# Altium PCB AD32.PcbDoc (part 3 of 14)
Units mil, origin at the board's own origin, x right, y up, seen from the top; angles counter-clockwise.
Board outline 7007.87 x 4368.85 mil, 12 copper layers (Top Layer, Int1 (GND), Int2 (AVDD), Int3 (DVDD), Int4 (GND), Int5 (ST), Int6 (SB), Int8 (AGND), Int7 (AVCC), Int9 (VCCA), Int10 (GND), Bottom Layer), stack 60.136 mil thick; 1350 components, 880 nets, 4712 pads, 2835 vias.
Unrouted connection lines stored in the file: 19.
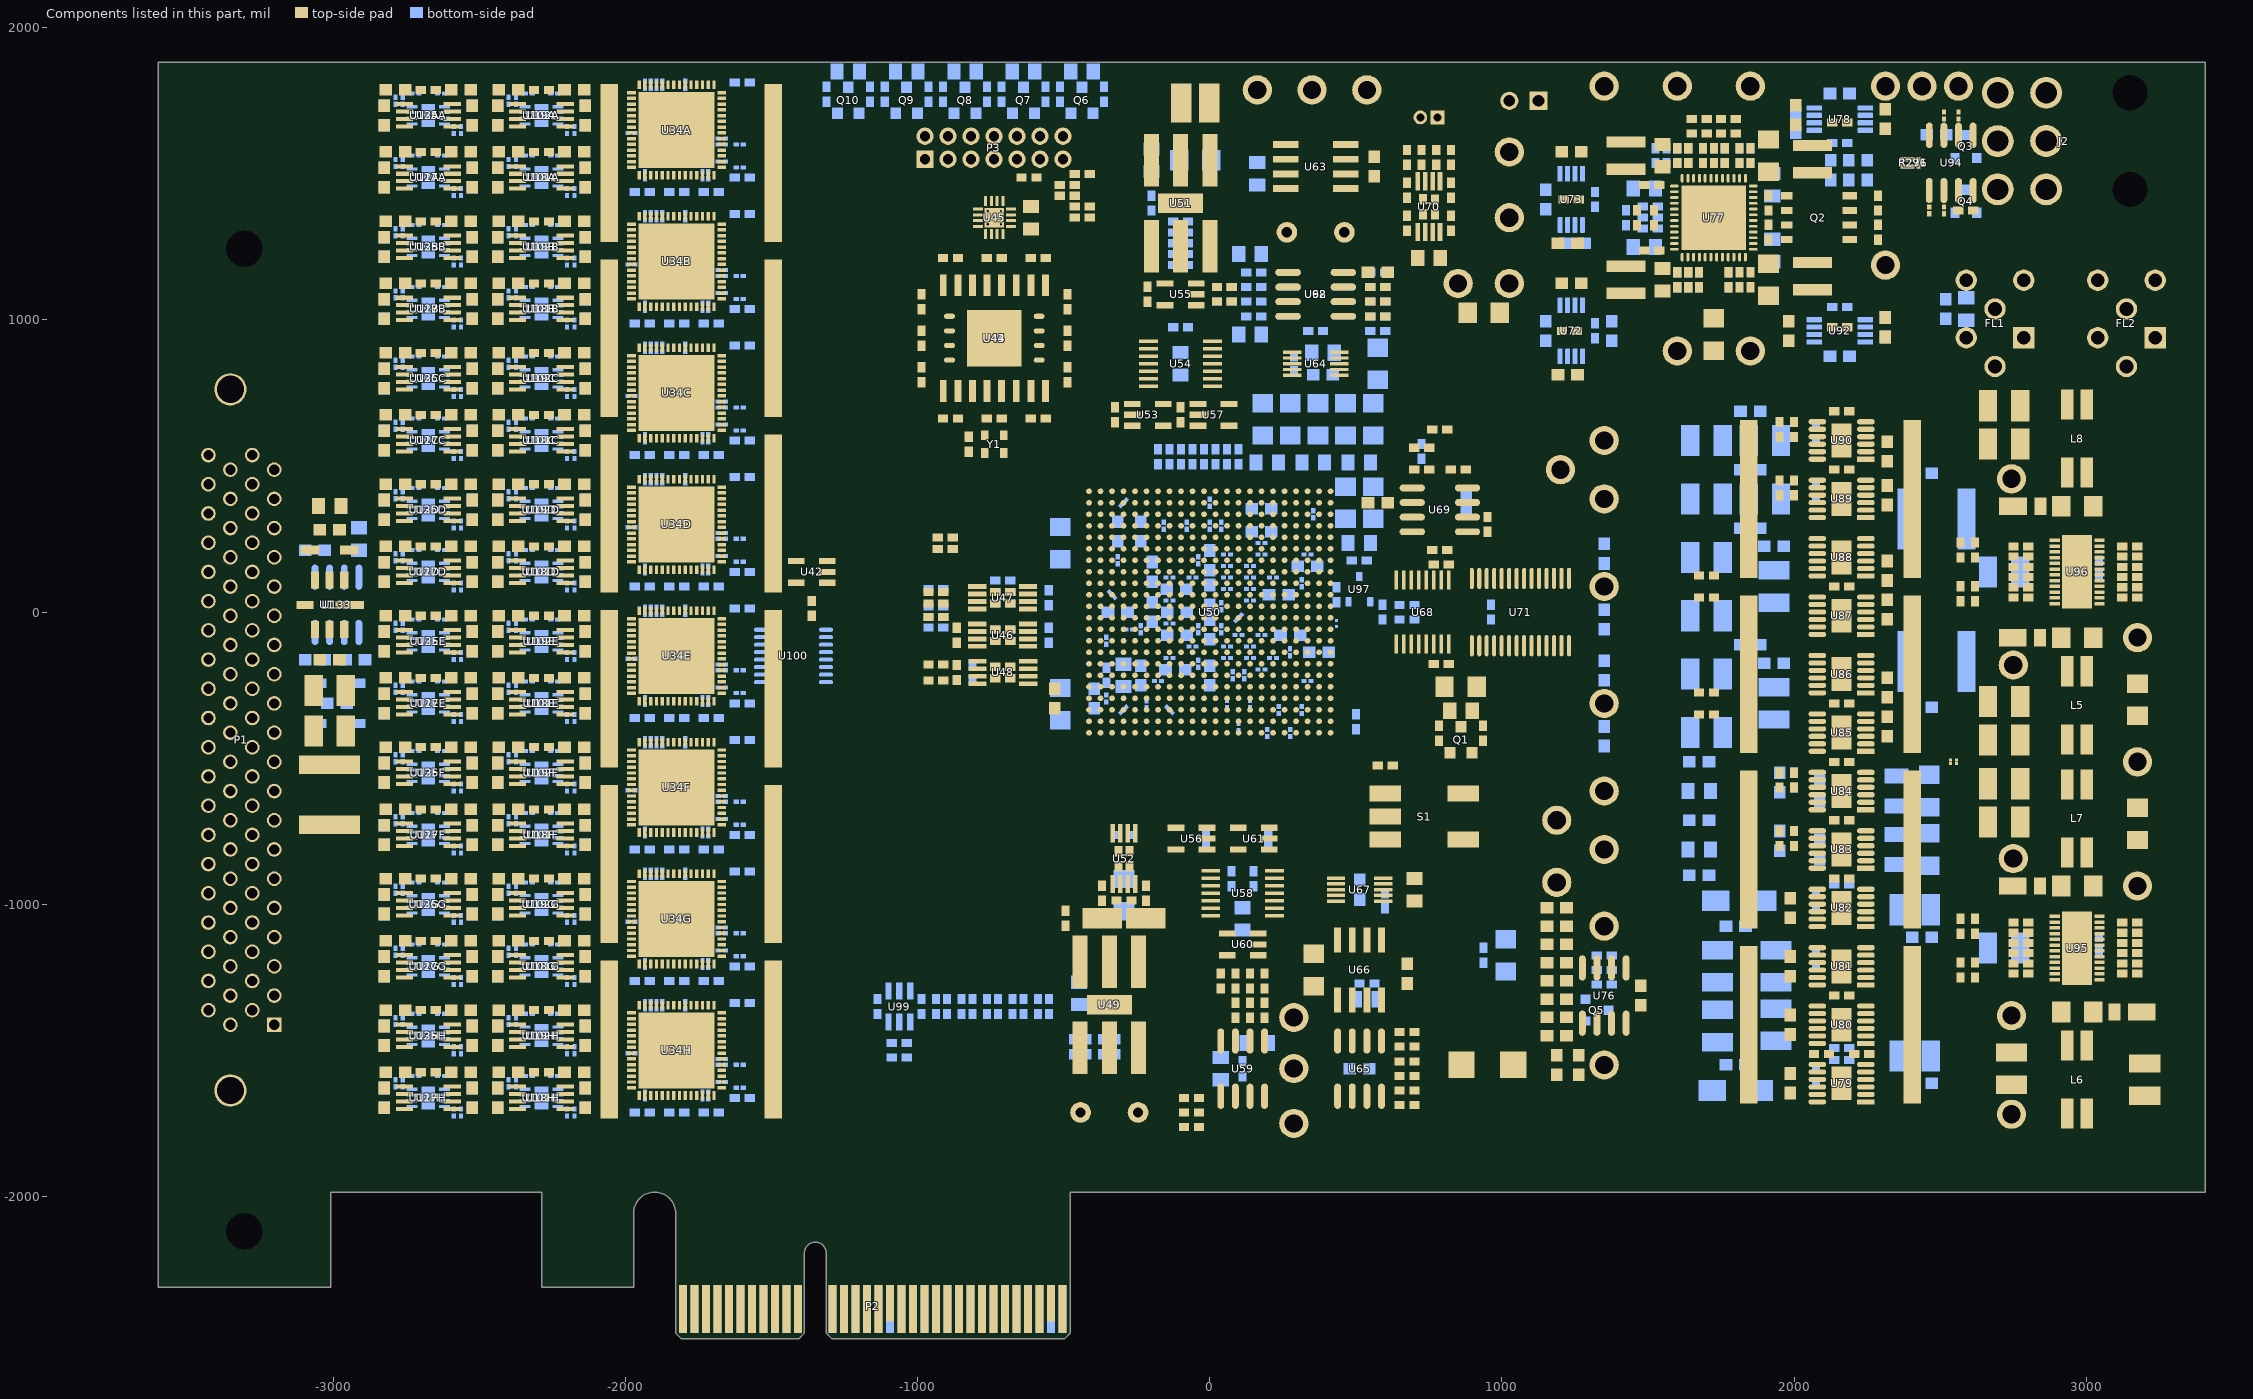
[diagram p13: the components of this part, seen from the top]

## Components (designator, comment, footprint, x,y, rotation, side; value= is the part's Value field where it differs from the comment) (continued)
R633A "10M" CR0603-0201 -2718.75,1562.5 r0 bottom (schematic designator R633)
R633B "10M" CR0603-0201 -2718.75,1112.5 r0 bottom (schematic designator R633)
R633C "10M" CR0603-0201 -2718.75,662.5 r0 bottom (schematic designator R633)
R633D "10M" CR0603-0201 -2718.75,212.5 r0 bottom (schematic designator R633)
R633E "10M" CR0603-0201 -2718.75,-237.5 r0 bottom (schematic designator R633)
R633F "10M" CR0603-0201 -2718.75,-687.5 r0 bottom (schematic designator R633)
R633G "10M" CR0603-0201 -2718.75,-1137.5 r0 bottom (schematic designator R633)
R633H "10M" CR0603-0201 -2718.75,-1587.5 r0 bottom (schematic designator R633)
R634A "10M" CR0603-0201 -2718.75,1775 r0 bottom (schematic designator R634)
R634B "10M" CR0603-0201 -2718.75,1325 r0 bottom (schematic designator R634)
R634C "10M" CR0603-0201 -2718.75,875 r0 bottom (schematic designator R634)
R634D "10M" CR0603-0201 -2718.75,425 r0 bottom (schematic designator R634)
R634E "10M" CR0603-0201 -2718.75,-25 r0 bottom (schematic designator R634)
R634F "10M" CR0603-0201 -2718.75,-475 r0 bottom (schematic designator R634)
R634G "10M" CR0603-0201 -2718.75,-925 r0 bottom (schematic designator R634)
R634H "10M" CR0603-0201 -2718.75,-1375 r0 bottom (schematic designator R634)
R649A "10k" CR1608-0603 -2825,1487.5 r270 bottom (schematic designator R649)
R649B "10k" CR1608-0603 -2825,1037.5 r270 bottom (schematic designator R649)
R649C "10k" CR1608-0603 -2825,587.5 r270 bottom (schematic designator R649)
R649D "10k" CR1608-0603 -2825,137.5 r270 bottom (schematic designator R649)
R649E "10k" CR1608-0603 -2825,-312.5 r270 bottom (schematic designator R649)
R649F "10k" CR1608-0603 -2825,-762.5 r270 bottom (schematic designator R649)
R649G "10k" CR1608-0603 -2825,-1212.5 r270 bottom (schematic designator R649)
R649H "10k" CR1608-0603 -2825,-1662.5 r270 bottom (schematic designator R649)
R657A "10k" CR1608-0603 -2825,1700 r270 bottom (schematic designator R657)
R657B "10k" CR1608-0603 -2825,1250 r270 bottom (schematic designator R657)
R657C "10k" CR1608-0603 -2825,800 r270 bottom (schematic designator R657)
R657D "10k" CR1608-0603 -2825,350 r270 bottom (schematic designator R657)
R657E "10k" CR1608-0603 -2825,-100 r270 bottom (schematic designator R657)
R657F "10k" CR1608-0603 -2825,-550 r270 bottom (schematic designator R657)
R657G "10k" CR1608-0603 -2825,-1000 r270 bottom (schematic designator R657)
R657H "10k" CR1608-0603 -2825,-1450 r270 bottom (schematic designator R657)
R665 "100" CR1608-0603 -3062.5,-162.5 r180 bottom
R666 "100" CR1608-0603 -3062.5,212.5 r180 bottom
S1 "B3SN-3112P" SW_SMD_6MM 600,-621.26 r0 top
TP1 "Testpoint" TP2#1 -97.5,1742.5 r0 top
TP2 "Testpoint" TP2#1 -2.5,1742.5 r0 top
TP3 "Testpoint" TP1-YLW#1 162.5,1787.5 r180 top
TP4 "Testpoint" TP1-RED 287.5,-1750 r90 top
TP5 "Testpoint" TP1-YLW#1 287.5,-1562.5 r270 top
TP6 "Testpoint" TP1-YLW#1 287.5,-1387.5 r270 top
TP7 "Testpoint" TP1-YLW#1 350,1787.5 r180 top
TP8 "Testpoint" TP1-RED 537.5,1787.5 r180 top
TP9 "Testpoint" TP1-RED 850,1125 r180 top
TP10 "Testpoint" TP1-RED 1025,1125 r180 top
TP11 "Testpoint" TP1-RED 1025,1350 r180 top
TP12 "Testpoint" TP1-RED 1025,1575 r180 top
TP13 "Testpoint" TP1-BLK 1187.5,-925 r90 top
TP14 "Testpoint" TP1-BLK 1187.5,-712.5 r90 top
TP15 "Testpoint" TP1-BLK 1200,487.5 r270 top
TP16 "Testpoint" TP1-WHT 1350,-1550 r270 top
TP17 "Testpoint" TP1-RED 1350,-1075 r270 top
TP18 "Testpoint" TP1-RED 1350,-812.5 r90 top
TP19 "Testpoint" TP1-RED 1350,-612.5 r90 top
TP20 "Testpoint" TP1-RED 1350,-312.5 r90 top
TP21 "Testpoint" TP1-RED 1350,87.5 r90 top
TP22 "Testpoint" TP1-RED 1350,387.5 r90 top
TP23 "Testpoint" TP1-RED 1350,587.5 r90 top
TP24 "Testpoint" TP1-BLK 1350,1800 r180 top
TP25 "Testpoint" TP1-BLK 1600,893.75 r90 top
TP26 "Testpoint" TP1-RED 1600,1800 r180 top
TP27 "Testpoint" TP1-YLW#2 1850,1801.97 r0 top
TP28 "Testpoint" TP1-RED 1850,893.75 r180 top
TP29 "Testpoint" TP1-RED 2312.5,1187.5 r180 top
TP30 "Testpoint" TP1-RED 2312.5,1800 r0 top
TP31 "Testpoint" TP1-RED 2437.5,1800 r0 top
TP32 "Testpoint" TP1-BLK 2562.5,1800 r180 top
TP33 "Testpoint" TP1-WHT 2743.75,-1718.75 r90 top
TP34 "Testpoint" TP1-BLK 2743.75,-1381.25 r90 top
TP35 "Testpoint" TP1-RED 2743.75,456.25 r90 top
TP36 "Testpoint" TP1-RED 2750,-843.75 r90 top
TP37 "Testpoint" TP1-RED 2750,-181.25 r90 top
TP38 "Testpoint" TP1-RED 3175,-937.5 r90 top
TP39 "Testpoint" TP1-RED 3175,-512.5 r90 top
TP40 "Testpoint" TP1-RED 3175,-87.5 r90 top
TP41 "Testpoint" TP2#2 -367.5,-1047.5 r270 bottom
TP42 "Testpoint" TP2#2 -220,-1047.5 r270 bottom
U1 "LTC6655BHLS8-4.096#PBF" FP-LS8-8-05-08-1852-MFG -3012.5,25 r270 top
U2A "THP210" UMAX8 -2675,1487.5 r90 top (schematic designator U2)
U2B "THP210" UMAX8 -2675,1037.5 r90 top (schematic designator U2)
U2C "THP210" UMAX8 -2675,587.5 r90 top (schematic designator U2)
U2D "THP210" UMAX8 -2675,137.5 r90 top (schematic designator U2)
U2E "THP210" UMAX8 -2675,-312.5 r90 top (schematic designator U2)
U2F "THP210" UMAX8 -2675,-762.5 r90 top (schematic designator U2)
U2G "THP210" UMAX8 -2675,-1212.5 r90 top (schematic designator U2)
U2H "THP210" UMAX8 -2675,-1662.5 r90 top (schematic designator U2)
U3A "THP210" UMAX8 -2675,1699.87 r90 top (schematic designator U3)
U3B "THP210" UMAX8 -2675,1249.87 r90 top (schematic designator U3)
U3C "THP210" UMAX8 -2675,799.87 r90 top (schematic designator U3)
U3D "THP210" UMAX8 -2675,349.87 r90 top (schematic designator U3)
U3E "THP210" UMAX8 -2675,-100.13 r90 top (schematic designator U3)
U3F "THP210" UMAX8 -2675,-550.13 r90 top (schematic designator U3)
U3G "THP210" UMAX8 -2675,-1000.13 r90 top (schematic designator U3)
U3H "THP210" UMAX8 -2675,-1450.13 r90 top (schematic designator U3)
U18A "THP210" UMAX8 -2287.5,1487.5 r90 top (schematic designator U18)
U18B "THP210" UMAX8 -2287.5,1037.5 r90 top (schematic designator U18)
U18C "THP210" UMAX8 -2287.5,587.5 r90 top (schematic designator U18)
U18D "THP210" UMAX8 -2287.5,137.5 r90 top (schematic designator U18)
U18E "THP210" UMAX8 -2287.5,-312.5 r90 top (schematic designator U18)
U18F "THP210" UMAX8 -2287.5,-762.5 r90 top (schematic designator U18)
U18G "THP210" UMAX8 -2287.5,-1212.5 r90 top (schematic designator U18)
U18H "THP210" UMAX8 -2287.5,-1662.5 r90 top (schematic designator U18)
U19A "THP210" UMAX8 -2287.5,1700 r90 top (schematic designator U19)
U19B "THP210" UMAX8 -2287.5,1250 r90 top (schematic designator U19)
U19C "THP210" UMAX8 -2287.5,800 r90 top (schematic designator U19)
U19D "THP210" UMAX8 -2287.5,350 r90 top (schematic designator U19)
U19E "THP210" UMAX8 -2287.5,-100 r90 top (schematic designator U19)
U19F "THP210" UMAX8 -2287.5,-550 r90 top (schematic designator U19)
U19G "THP210" UMAX8 -2287.5,-1000 r90 top (schematic designator U19)
U19H "THP210" UMAX8 -2287.5,-1450 r90 top (schematic designator U19)
U34A "AD4134BCPZ" CP-56-9_ADI -1825,1650 r180 top locked (schematic designator U34)
U34B "AD4134BCPZ" CP-56-9_ADI -1825,1200 r180 top locked (schematic designator U34)
U34C "AD4134BCPZ" CP-56-9_ADI -1825,750 r180 top locked (schematic designator U34)
U34D "AD4134BCPZ" CP-56-9_ADI -1825,300 r180 top (schematic designator U34)
U34E "AD4134BCPZ" CP-56-9_ADI -1825,-150 r180 top (schematic designator U34)
U34F "AD4134BCPZ" CP-56-9_ADI -1825,-600 r180 top locked (schematic designator U34)
U34G "AD4134BCPZ" CP-56-9_ADI -1825,-1050 r180 top locked (schematic designator U34)
U34H "AD4134BCPZ" CP-56-9_ADI -1825,-1500 r180 top locked (schematic designator U34)
U42 "SN65LVDT2" SO-G5/E2.4 -1362.5,137.5 r90 top
U43 "MT25QU512ABB8ESF-0SIT" FP-002-15547-MFG -737.5,937.5 r90 top
U44 "MT25QU512ABB1EW9-0SIT" FP-002-18827-MFG -737.5,937.5 r180 top
U45 "8P34S1102" QFN50P300X300X100-17N -737.5,1350 r180 top locked
U46 "SN65LVDS100D" MSOP8 -708.66,-78.74 r270 top
U47 "SN65LVDS100D" MSOP8 -708.66,49.21 r270 top
U48 "SN65LVDS100D" MSOP8 -708.66,-206.69 r90 top
U49 "67.108864MHz" BomarSiTime -343.75,-1343.49 r90 top locked
U50 "XC7A200T-2FBG484I" FBG484 0,0 r180 top locked
U51 "47.934903MHz" BomarSiTime -100,1400 r90 top locked
U52 "SN65LVDS100D" MSOP8 -293.75,-843.75 r0 top
U53 "SN65LVDT2" SO-G5/E2.4 -212.5,675 r270 top
U54 "SN74LVC74APWR" TSSOP14 -100,850 r270 top locked
U55 "SN74LVC1G00" SO-G5/E2.4 -100,1087.5 r90 top
U56 "SN65LVDT2" SO-G5/E2.4 -62.5,-775 r90 top
U57 "SN65LVDT2" SO-G5/E2.4 12.5,675 r270 top
U58 "SN74LVC74APWR" TSSOP14 112.5,-962.5 r90 top
U59 "OP284FS" SO-8_N 112.5,-1562.5 r270 top
U60 "SN74LVC1G00" SO-G5/E2.4 112.5,-1137.5 r90 top
U61 "SN65LVDT2" SO-G5/E2.4 150,-775 r90 top
U62 "OP284FS" SO-8_N 362.5,1087.5 r0 top
U63 "ADR4525" SO-G8 362.5,1525 r270 top
U64 "AD7685" TSSO3x5-G10 362.5,850 r270 top
U65 "OP284FS" SO-8_N 512.5,-1562.5 r90 top
U66 "ADR4525" SO-G8 512.5,-1225 r0 top
U67 "AD7685" TSSO3x5-G10 512.5,-950 r90 top
U68 "SN74LVC4T245" TSSOP16 728.35,0 r180 top locked
U69 "OP284FS" SO-8_N 787.5,350 r180 top
U70 "SN65LVDS100D" MSOP8 750,1387.5 r180 top
U71 "ADG706BRU" ADI-RU-28_M 1062.99,0 r270 top locked
U72 "INA333AIDGKR" DGK0008A_N 1237.5,962.5 r270 bottom
U73 "INA333AIDGKR" DGK0008A_N 1237.5,1412.5 r270 bottom
U76 "OP284FS" SO-8_N 1350,-1312.5 r90 top
U77 "ADP5052ACPZ-R7" CP-48-13_L 1725,1350 r0 top
U78 "INA333AIDGKR" DGK0008A_N 2156.25,1687.5 r180 bottom
U79 "LT3094IMSE#PBF" FP-MSE-12-05-08-1666-IPC_B 2162.5,-1612.5 r180 top locked
U80 "LT3094IMSE#PBF" FP-MSE-12-05-08-1666-IPC_B 2162.5,-1412.5 r180 top locked
U81 "LT3045EMSE-1#PBF" FP-MSE-12-05-08-1666-IPC_B 2162.5,-1212.5 r180 top locked
U82 "LT3045EMSE-1#PBF" FP-MSE-12-05-08-1666-IPC_B 2162.5,-1012.5 r180 top locked
U83 "LT3045EMSE-1#PBF" FP-MSE-12-05-08-1666-IPC_B 2162.5,-812.5 r180 top locked
U84 "LT3045EMSE-1#PBF" FP-MSE-12-05-08-1666-IPC_B 2162.5,-612.5 r180 top locked
U85 "LT3045EMSE-1#PBF" FP-MSE-12-05-08-1666-IPC_B 2162.5,-412.5 r180 top locked
U86 "LT3045EMSE-1#PBF" FP-MSE-12-05-08-1666-IPC_B 2162.5,-212.5 r180 top locked
U87 "LT3045EMSE-1#PBF" FP-MSE-12-05-08-1666-IPC_B 2162.5,-12.5 r180 top locked
U88 "LT3045EMSE-1#PBF" FP-MSE-12-05-08-1666-IPC_B 2162.5,187.5 r180 top locked
U89 "LT3045EMSE-1#PBF" FP-MSE-12-05-08-1666-IPC_B 2162.5,387.5 r180 top locked
U90 "LT3045EMSE-1#PBF" FP-MSE-12-05-08-1666-IPC_B 2162.5,587.5 r180 top locked
U92 "INA333AIDGKR" DGK0008A_N 2155.97,962.5 r0 bottom
U94 "OP284FS" SO-8_N 2537.5,1537.5 r270 top
U95 "LT8582EDKD" DFN-24_DKD 2968.75,-1150 r0 top
U96 "LT8582EDKD" DFN-24_DKD 2968.75,137.5 r0 top
U97 "REF3012AIDBZT" DBZ0003A_L 511.81,78.74 r90 bottom
U98 "OP284FS" SO-8_N 362.5,1087.5 r0 bottom locked
U99 "SN74AVC1T45" SO-G6/E2.4 -1062.5,-1350 r0 bottom
U100 "Si53365-B-GT" SLAB-TSSOP-16_L -1425,-150 r180 bottom
U101A "ADA4084-2ACPZ-R7" SON-8 -2287.5,1487.5 r0 bottom (schematic designator U101)
U101B "ADA4084-2ACPZ-R7" SON-8 -2287.5,1037.5 r0 bottom (schematic designator U101)
U101C "ADA4084-2ACPZ-R7" SON-8 -2287.5,587.5 r0 bottom (schematic designator U101)
U101D "ADA4084-2ACPZ-R7" SON-8 -2287.5,137.5 r0 bottom (schematic designator U101)
U101E "ADA4084-2ACPZ-R7" SON-8 -2287.5,-312.5 r0 bottom (schematic designator U101)
U101F "ADA4084-2ACPZ-R7" SON-8 -2287.5,-762.5 r0 bottom (schematic designator U101)
U101G "ADA4084-2ACPZ-R7" SON-8 -2287.5,-1212.5 r0 bottom (schematic designator U101)
U101H "ADA4084-2ACPZ-R7" SON-8 -2287.5,-1662.5 r0 bottom locked (schematic designator U101)
U102A "ADA4084-2ACPZ-R7" SON-8 -2287.5,1700 r0 bottom (schematic designator U102)
U102B "ADA4084-2ACPZ-R7" SON-8 -2287.5,1250 r0 bottom (schematic designator U102)
U102C "ADA4084-2ACPZ-R7" SON-8 -2287.5,800 r0 bottom (schematic designator U102)
U102D "ADA4084-2ACPZ-R7" SON-8 -2287.5,350 r0 bottom (schematic designator U102)
U102E "ADA4084-2ACPZ-R7" SON-8 -2287.5,-100 r0 bottom (schematic designator U102)
U102F "ADA4084-2ACPZ-R7" SON-8 -2287.5,-550 r0 bottom (schematic designator U102)
U102G "ADA4084-2ACPZ-R7" SON-8 -2287.5,-1000 r0 bottom (schematic designator U102)
U102H "ADA4084-2ACPZ-R7" SON-8 -2287.5,-1450 r0 bottom locked (schematic designator U102)
U117A "ADA4084-2ACPZ-R7" SON-8 -2675,1487.5 r0 bottom (schematic designator U117)
U117B "ADA4084-2ACPZ-R7" SON-8 -2675,1037.5 r0 bottom (schematic designator U117)
U117C "ADA4084-2ACPZ-R7" SON-8 -2675,587.5 r0 bottom (schematic designator U117)
U117D "ADA4084-2ACPZ-R7" SON-8 -2675,137.5 r0 bottom (schematic designator U117)
U117E "ADA4084-2ACPZ-R7" SON-8 -2675,-312.5 r0 bottom (schematic designator U117)
U117F "ADA4084-2ACPZ-R7" SON-8 -2675,-762.5 r0 bottom (schematic designator U117)
U117G "ADA4084-2ACPZ-R7" SON-8 -2675,-1212.5 r0 bottom (schematic designator U117)
U117H "ADA4084-2ACPZ-R7" SON-8 -2675,-1662.5 r0 bottom locked (schematic designator U117)
U125A "ADA4084-2ACPZ-R7" SON-8 -2675,1699.87 r0 bottom (schematic designator U125)
U125B "ADA4084-2ACPZ-R7" SON-8 -2675,1249.87 r0 bottom (schematic designator U125)
U125C "ADA4084-2ACPZ-R7" SON-8 -2675,799.87 r0 bottom (schematic designator U125)
U125D "ADA4084-2ACPZ-R7" SON-8 -2675,349.87 r0 bottom (schematic designator U125)
U125E "ADA4084-2ACPZ-R7" SON-8 -2675,-100.13 r0 bottom (schematic designator U125)
U125F "ADA4084-2ACPZ-R7" SON-8 -2675,-550.13 r0 bottom (schematic designator U125)
U125G "ADA4084-2ACPZ-R7" SON-8 -2675,-1000.13 r0 bottom (schematic designator U125)
U125H "ADA4084-2ACPZ-R7" SON-8 -2675,-1450.13 r0 bottom locked (schematic designator U125)
U133 "OP284FS" SO-8_N -2987.5,25 r90 bottom locked
W1 "Net tie" NETTIE1_SMDTOP 2555,-518.75 r180 top net-tie value=NL
W2 "Net tie" NETTIE1_SMDTOP 2555,-506.25 r180 top net-tie value=NL
W3 "NL" NETTIE1_SMDTOP 433.07,-48.87 r90 bottom net-tie
Y1 "DSC1001DI1-100.0000T" FP-CDFN2520-4LD-PL-1-MFG -737.5,575 r90 top

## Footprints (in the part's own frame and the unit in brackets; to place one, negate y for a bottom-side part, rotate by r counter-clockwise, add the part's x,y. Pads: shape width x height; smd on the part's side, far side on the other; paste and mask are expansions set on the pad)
2MM_HDR2X7_RA [mm] "Connector; 2mm Header; 7x2 Position, RA"
  rect 1.5x1.5 hole 0.9: 1(0,0)
  round 1.5 hole 0.9: 2(0,2) 3(2,0) 4(2,2) 5(4,0) 6(4,2) 7(6,0) 8(6,2) 9(8,0) 10(8,2) 11(10,0) 12(10,2) 13(12,0) 14(12,2)
  silkscreen extent -2.29,-1.27 14.22,8.38, body extent -2.32,-0.27 14.33,8.38, height 6.3
455580003 [mm]
  round 2.775 hole 1.85: 1(0,0) 2(4.191,0) 3(8.4,0) 4(0,-4.2) 5(4.2,-4.2) 6(8.4,-4.2)
  round 1.525 hole 3.05 unplated: MH1(0,7.3) MH2(8.4,7.3)
  silkscreen extent -2.7,1.1 11.1,13.9, body extent -3.14,-4.78 11.06,13.86, height 11.53
ADI-RU-28_M [mm] "SOP, 28-Leads, Body 9.7x4.4mm, Pitch 0.65mm, IPC Low Density"
  oval 1.85x0.35 smd: 1(-2.925,4.225) 2(-2.925,3.575) 3(-2.925,2.925) 4(-2.925,2.275) 5(-2.925,1.625) 6(-2.925,0.975) 7(-2.925,0.325) 8(-2.925,-0.325) 9(-2.925,-0.975) 10(-2.925,-1.625) 11(-2.925,-2.275) 12(-2.925,-2.925) 13(-2.925,-3.575) 14(-2.925,-4.225) 15(2.925,-4.225) 16(2.925,-3.575) 17(2.925,-2.925) 18(2.925,-2.275) 19(2.925,-1.625) 20(2.925,-0.975) 21(2.925,-0.325) 22(2.925,0.325) 23(2.925,0.975) 24(2.925,1.625) 25(2.925,2.275) 26(2.925,2.925) 27(2.925,3.575) 28(2.925,4.225)
  silkscreen extent -3.05,-4.9 1.6,5.08, body extent -2.25,-4.9 2.25,4.9, height 1.2
BomarSiTime [mm] "VCXO 14.3 x 8.7 mm or 7.0 x 5.0 mm"
  rect 4.572x1.3 smd: 1(-3.74,2.54) 2(-3.74,0) 3(-3.74,-2.54) 4(3.727,-2.54) 5(3.727,0) 6(3.727,2.54)
  rect 1.7x3.9 smd: 7(-0.007,0)
  silkscreen extent -6.81,-7.21 4.9,7.29, body extent -4.76,-7.11 4.79,7.19, height 5.9
CC0603-0201 [mil] "Chip Capacitor; Body 0.6 x 0.3 mm (LxW typ)"
  rect 17.97x14.28 smd mask+2: 1(-11.94,0) 2(11.94,0)
  body extent -12,-6 12,6, height 13
CC1005-0402 [mm] "Chip Capacitor; Body 1.0 x 0.5 mm (LxW typ)"
  rect 0.9x0.7 smd: 1(-0.65,0) 2(0.65,0)
  body extent -0.52,-0.28 0.52,0.27, height 0.55
CC1608-0603 [mm] "Chip Capacitor; Body 1.6 x 0.8 mm (LxW typ)"
  rect 1.1x1 smd: 1(-0.85,0) 2(0.85,0)
  silkscreen extent -1.7,-0.4 -1.7,0.4, body extent -0.87,-0.48 0.87,0.48, height 0.87
CC2013-0805 [mm] "Chip Capacitor; Body 2.0 x 1.3 mm (LxW typ)"
  rect 1.15x1.4 smd: 1(-0.975,0) 2(0.975,0)
  silkscreen extent -1.85,-0.6 -1.85,0.6, body extent -1.1,-0.72 1.1,0.73, height 0.88
CC3216-1206 [mm] "Chip Capacitor; Body 3.2 x 1.6 mm (LxW typ)"
  rect 1.6x1.8 smd: 1(-1.4,0) 2(1.4,0)
  silkscreen extent -0.3,-0.8 0.3,0.8, body extent -1.85,-0.97 1.85,0.97, height 0.88
CC3225-1210 [mm] "Chip Capacitor; Body 3.2 x 2.5 mm (LxW typ)"
  rect 1.6x2.7 smd: 1(-1.4,0) 2(1.4,0)
  silkscreen extent -0.3,-1.25 0.3,1.25, body extent -1.85,-1.45 1.85,1.45, height 1.4
CC5650-2220 [mm] "Chip Capacitor, Body 5.6 x 5.0mm (LxW typ)"
  rect 1.6x5.3 smd: 1(-2.6,0) 2(2.6,0)
  silkscreen extent -1.4,-2.55 1.4,2.55, body extent -3.05,-2.7 3.05,2.7, height 1.8
CL2520-1008 [mm] "Chip Inductor; Body 2.54 x 2.0 mm (LxW typ)"
  rect 1.3x2.1 smd: 1(-1.3,0) 2(1.3,0)
  silkscreen extent -2.25,-1 -2.25,1, body extent -1.46,-1.39 1.46,1.4, height 2.02
CP-48-13_L [mm] "QFN, 48-Leads, Body 7x7mm, Pitch 0.5mm, Thermal Pad 5.6x5.6mm, IPC High Density"
  oval 0.75x0.25 smd: 1(-3.425,2.75) 2(-3.425,2.25) 3(-3.425,1.75) 4(-3.425,1.25) 5(-3.425,0.75) 6(-3.425,0.25) 7(-3.425,-0.25) 8(-3.425,-0.75) 9(-3.425,-1.25) 10(-3.425,-1.75) 11(-3.425,-2.25) 12(-3.425,-2.75) 25(3.425,-2.75) 26(3.425,-2.25) 27(3.425,-1.75) 28(3.425,-1.25) 29(3.425,-0.75) 30(3.425,-0.25) 31(3.425,0.25) 32(3.425,0.75) 33(3.425,1.25) 34(3.425,1.75) 35(3.425,2.25) 36(3.425,2.75)
  oval 0.25x0.75 smd: 13(-2.75,-3.425) 14(-2.25,-3.425) 15(-1.75,-3.425) 16(-1.25,-3.425) 17(-0.75,-3.425) 18(-0.25,-3.425) 19(0.25,-3.425) 20(0.75,-3.425) 21(1.25,-3.425) 22(1.75,-3.425) 23(2.25,-3.425) 24(2.75,-3.425) 37(2.75,3.425) 38(2.25,3.425) 39(1.75,3.425) 40(1.25,3.425) 41(0.75,3.425) 42(0.25,3.425) 43(-0.25,3.425) 44(-0.75,3.425) 45(-1.25,3.425) 46(-1.75,3.425) 47(-2.25,3.425) 48(-2.75,3.425)
  rect 5.6x5.6 smd paste-2.7: 49(0,0)
  silkscreen extent -4.47,-3.7 3.7,3.7
CP-56-9_ADI [mm] "56-Lead LFCSP (8mm x 8mm w/ EP)"
  rect 0.755x0.3 smd: 1(-3.927,3.25) 2(-3.927,2.75) 3(-3.927,2.25) 4(-3.927,1.75) 5(-3.927,1.25) 6(-3.927,0.75) 7(-3.927,0.25) 8(-3.927,-0.25) 9(-3.927,-0.75) 10(-3.927,-1.25) 11(-3.927,-1.75) 12(-3.927,-2.25) 13(-3.927,-2.75) 14(-3.927,-3.25) 29(3.927,-3.25) 30(3.927,-2.75) 31(3.927,-2.25) 32(3.927,-1.75) 33(3.927,-1.25) 34(3.927,-0.75) 35(3.927,-0.25) 36(3.927,0.25) 37(3.927,0.75) 38(3.927,1.25) 39(3.927,1.75) 40(3.927,2.25) 41(3.927,2.75) 42(3.927,3.25)
  rect 0.3x0.755 smd: 15(-3.25,-3.927) 16(-2.75,-3.927) 17(-2.25,-3.927) 18(-1.75,-3.927) 19(-1.25,-3.927) 20(-0.75,-3.927) 21(-0.25,-3.927) 22(0.25,-3.927) 23(0.75,-3.927) 24(1.25,-3.927) 25(1.75,-3.927) 26(2.25,-3.927) 27(2.75,-3.927) 28(3.25,-3.927) 43(3.25,3.927) 44(2.75,3.927) 45(2.25,3.927) 46(1.75,3.927) 47(1.25,3.927) 48(0.75,3.927) 49(0.25,3.927) 50(-0.25,3.927) 51(-0.75,3.927) 52(-1.25,3.927) 53(-1.75,3.927) 54(-2.25,3.927) 55(-2.75,3.927) 56(-3.25,3.927)
  rect 6.6x6.6 smd paste-3.3: 57(0,0)
  silkscreen extent -4.81,-4.81 4.81,4.81, body extent -4,-4 4,4, height 0.78
CR0603-0201 [mil] "Chip Resistor; Body 0.6 x 0.3 mm (LxW typ)"
  rect 17.97x14.28 smd mask+2: 1(-11.94,0) 2(11.94,0)
  body extent -12,-6 12,6, height 10
CR0816-0306-4P [mm] "4-terminal current sensor"
  rect 0.4x1.2 smd: 1(-0.3,-0.275) 4(0.3,-0.275)
  rect 0.4x0.35 smd: 2(-0.3,0.7) 3(0.3,0.7)
  silkscreen extent -0.77,0.65 -0.67,0.75, body extent -0.39,-0.8 0.39,0.8, height 0.5
CR1005-0402 [mm] "Chip Resistor; Body 1.1 x 0.5 mm (LxW typ)"
  rect 0.9x0.7 smd: 1(-0.65,0) 2(0.65,0)
  body extent -0.5,-0.25 0.5,0.25, height 0.32
CR1608-0603 [mm] "Chip Resistor; Body 1.6 x 0.8 mm (LxW typ)"
  rect 1.1x1 smd: 1(-0.85,0) 2(0.85,0)
  body extent -0.76,-0.43 0.79,0.42, height 0.46
DBZ0003A_L [mm] "SOT23, 3-Leads, Body 3.04x1.4mm, Pitch 0.95mm, IPC High Density"
  rrect18% 0.8x0.55 smd: 1(-1.1,0.95) 2(-1.1,-0.95) 3(1.1,0)
  silkscreen extent -1.22,-1.5 0.7,1.9, body extent -1.26,-1.46 1.26,1.46, height 0.96
DFN-24_DKD [mil] "24-Lead Plastic DFN (7mm × 3mm)"
  rect 35x12 smd: 1(-76.5,108.27) 2(-76.5,88.58) 3(-76.5,68.9) 4(-76.5,49.21) 5(-76.5,29.53) 6(-76.5,9.84) 7(-76.5,-9.84) 8(-76.5,-29.53) 9(-76.5,-49.21) 10(-76.5,-68.9) 11(-76.5,-88.58) 12(-76.5,-108.27) 13(76.5,-108.27) 14(76.5,-88.58) 15(76.5,-68.9) 16(76.5,-49.21) 17(76.5,-29.53) 18(76.5,-9.84) 19(76.5,9.84) 20(76.5,29.53) 21(76.5,49.21) 22(76.5,68.9) 23(76.5,88.58) 24(76.5,108.27)
  rect 102.87x252.09 smd paste+0 mask+0: 25(0,0)
  silkscreen extent -109,-145 86,145, body extent -81,-140 81,140, height 32
DGK0008A_N [mm] "TSOP, 8-Leads, Body 3.1x3.1mm, Pitch 0.65mm, IPC Medium Density"
  rrect22% 1.35x0.45 smd: 1(-2.225,0.975) 2(-2.225,0.325) 3(-2.225,-0.325) 4(-2.225,-0.975) 5(2.225,-0.975) 6(2.225,-0.325) 7(2.225,0.325) 8(2.225,0.975)
  silkscreen extent -2.35,-1.55 1.15,1.9, body extent -2.45,-1.5 2.45,1.5, height 0.94
DO-PowerDI123 [mm] "POWERDI123, Body 3.7 x 1.8 mm, inc. leads (LxW)"
  rect 1.05x1.5 smd: 1(-1.525,0)
  rect 2.4x1.5 smd: 2(0.85,0)
  silkscreen extent -2.29,-1.02 2.29,1.02, body extent -1.85,-0.89 1.85,0.89, height 0.98
DO-SMA [mm] "DO-214-AC/SMA; 2 C-Bend Leads; Body 5 x 2.7 mm, inc. leads (LxW)"
  rect 2.4x1.8 smd: 1(-2.05,0) 2(2.05,0)
  silkscreen extent -3.65,-1.3 3.95,1.3, body extent -2.74,-1.4 2.74,1.4, height 2.41
DO-SMB [mm] "DO-214-AA/SMB; 2 C-Bend Leads; Body 5.3 x 3.6 mm, inc. leads (LxW)"
  rect 2.3x2.3 smd: 1(-2.25,0) 2(2.25,0)
  silkscreen extent -3.8,-1.55 4.1,1.55, body extent -2.75,-1.95 2.75,1.95, height 2.45
DO-SOD123 [mm] "SOD-123; 2 Leads; Body 2.7 x 1.6 mm, (LxW)"
  rect 1.6x0.8 smd: 1(-1.7,0) 2(1.7,0)
  silkscreen extent -1.45,-0.85 1.45,0.85, body extent -1.95,-0.9 1.95,0.9, height 1.18
ECQPZ085045-5.0 [mm] "Polypropylene Film Capacitor; Body 8.5 x 4.5 mm (LxW typ); 5.0mm lead spacing"
  round 1.8 hole 0.9: 1(0,0) 2(5,0)
  silkscreen extent -1.75,-2.25 6.75,2.25
ECQPZ120060-5.0 [mm] "Polypropylene Film Capacitor; Body 12.0 x 6.0 mm (LxW typ); 5.0mm lead spacing"
  round 1.8 hole 0.9: 1(0,0) 2(5,0)
  silkscreen extent -3.5,-3 8.5,3
FBG484 [mm] "BGA, 484-Balls, Body 23x23mm, Pitch 1.0mm"
  round 0.5 smd: A1(-10.5,10.5) A2(-9.5,10.5) A3(-8.5,10.5) A4(-7.5,10.5) A5(-6.5,10.5) A6(-5.5,10.5) A7(-4.5,10.5) A8(-3.5,10.5) A9(-2.5,10.5) A10(-1.5,10.5) A11(-0.5,10.5) A12(0.5,10.5) A13(1.5,10.5) A14(2.5,10.5) A15(3.5,10.5) A16(4.5,10.5) A17(5.5,10.5) A18(6.5,10.5) A19(7.5,10.5) A20(8.5,10.5) A21(9.5,10.5) A22(10.5,10.5) AA1(-10.5,-9.5) AA2(-9.5,-9.5) AA3(-8.5,-9.5) AA4(-7.5,-9.5) AA5(-6.5,-9.5) AA6(-5.5,-9.5) AA7(-4.5,-9.5) AA8(-3.5,-9.5) AA9(-2.5,-9.5) AA10(-1.5,-9.5) AA11(-0.5,-9.5) AA12(0.5,-9.5) AA13(1.5,-9.5) AA14(2.5,-9.5) AA15(3.5,-9.5) AA16(4.5,-9.5) AA17(5.5,-9.5) AA18(6.5,-9.5) AA19(7.5,-9.5) AA20(8.5,-9.5) AA21(9.5,-9.5) AA22(10.5,-9.5) AB1(-10.5,-10.5) AB2(-9.5,-10.5) AB3(-8.5,-10.5) AB4(-7.5,-10.5) AB5(-6.5,-10.5) AB6(-5.5,-10.5) AB7(-4.5,-10.5) AB8(-3.5,-10.5) AB9(-2.5,-10.5) AB10(-1.5,-10.5) AB11(-0.5,-10.5) AB12(0.5,-10.5) AB13(1.5,-10.5) AB14(2.5,-10.5) AB15(3.5,-10.5) AB16(4.5,-10.5) AB17(5.5,-10.5) AB18(6.5,-10.5) AB19(7.5,-10.5) AB20(8.5,-10.5) AB21(9.5,-10.5) AB22(10.5,-10.5) B1(-10.5,9.5) B2(-9.5,9.5) B3(-8.5,9.5) B4(-7.5,9.5) B5(-6.5,9.5) B6(-5.5,9.5) B7(-4.5,9.5) B8(-3.5,9.5) B9(-2.5,9.5) B10(-1.5,9.5) B11(-0.5,9.5) B12(0.5,9.5) B13(1.5,9.5) B14(2.5,9.5) B15(3.5,9.5) B16(4.5,9.5) B17(5.5,9.5) B18(6.5,9.5) B19(7.5,9.5) B20(8.5,9.5) B21(9.5,9.5) B22(10.5,9.5) C1(-10.5,8.5) C2(-9.5,8.5) C3(-8.5,8.5) C4(-7.5,8.5) C5(-6.5,8.5) C6(-5.5,8.5) C7(-4.5,8.5) C8(-3.5,8.5) C9(-2.5,8.5) C10(-1.5,8.5) C11(-0.5,8.5) C12(0.5,8.5) C13(1.5,8.5) C14(2.5,8.5) C15(3.5,8.5) C16(4.5,8.5) C17(5.5,8.5) C18(6.5,8.5) C19(7.5,8.5) C20(8.5,8.5) C21(9.5,8.5) C22(10.5,8.5) D1(-10.5,7.5) D2(-9.5,7.5) D3(-8.5,7.5) D4(-7.5,7.5) D5(-6.5,7.5) D6(-5.5,7.5) D7(-4.5,7.5) D8(-3.5,7.5) D9(-2.5,7.5) D10(-1.5,7.5) D11(-0.5,7.5) D12(0.5,7.5) D13(1.5,7.5) D14(2.5,7.5) D15(3.5,7.5) D16(4.5,7.5) D17(5.5,7.5) D18(6.5,7.5) D19(7.5,7.5) D20(8.5,7.5) D21(9.5,7.5) D22(10.5,7.5) E1(-10.5,6.5) E2(-9.5,6.5) E3(-8.5,6.5) E4(-7.5,6.5) E5(-6.5,6.5) E6(-5.5,6.5) E7(-4.5,6.5) E8(-3.5,6.5) E9(-2.5,6.5) E10(-1.5,6.5) E11(-0.5,6.5) E12(0.5,6.5) E13(1.5,6.5) E14(2.5,6.5) E15(3.5,6.5) E16(4.5,6.5) E17(5.5,6.5) E18(6.5,6.5) E19(7.5,6.5) E20(8.5,6.5) E21(9.5,6.5) E22(10.5,6.5) F1(-10.5,5.5) F2(-9.5,5.5) F3(-8.5,5.5) F4(-7.5,5.5) F5(-6.5,5.5) F6(-5.5,5.5) F7(-4.5,5.5) F8(-3.5,5.5) F9(-2.5,5.5) F10(-1.5,5.5) F11(-0.5,5.5) F12(0.5,5.5) F13(1.5,5.5) F14(2.5,5.5) F15(3.5,5.5) F16(4.5,5.5) F17(5.5,5.5) F18(6.5,5.5) F19(7.5,5.5) F20(8.5,5.5) F21(9.5,5.5) F22(10.5,5.5) G1(-10.5,4.5) G2(-9.5,4.5) G3(-8.5,4.5) G4(-7.5,4.5) G5(-6.5,4.5) G6(-5.5,4.5) G7(-4.5,4.5) G8(-3.5,4.5) G9(-2.5,4.5) G10(-1.5,4.5) G11(-0.5,4.5) G12(0.5,4.5) G13(1.5,4.5) G14(2.5,4.5) G15(3.5,4.5) G16(4.5,4.5) G17(5.5,4.5) G18(6.5,4.5) G19(7.5,4.5) G20(8.5,4.5) G21(9.5,4.5) G22(10.5,4.5) H1(-10.5,3.5) H2(-9.5,3.5) H3(-8.5,3.5) H4(-7.5,3.5) H5(-6.5,3.5) H6(-5.5,3.5) H7(-4.5,3.5) H8(-3.5,3.5) H9(-2.5,3.5) H10(-1.5,3.5) H11(-0.5,3.5) H12(0.5,3.5) H13(1.5,3.5) H14(2.5,3.5) H15(3.5,3.5) H16(4.5,3.5) H17(5.5,3.5) H18(6.5,3.5) H19(7.5,3.5) H20(8.5,3.5) H21(9.5,3.5) H22(10.5,3.5) J1(-10.5,2.5) J2(-9.5,2.5) J3(-8.5,2.5) J4(-7.5,2.5) J5(-6.5,2.5) J6(-5.5,2.5) J7(-4.5,2.5) J8(-3.5,2.5) J9(-2.5,2.5) J10(-1.5,2.5) J11(-0.5,2.5) J12(0.5,2.5) J13(1.5,2.5) J14(2.5,2.5) J15(3.5,2.5) J16(4.5,2.5) J17(5.5,2.5) J18(6.5,2.5) J19(7.5,2.5) J20(8.5,2.5) J21(9.5,2.5) J22(10.5,2.5) K1(-10.5,1.5) K2(-9.5,1.5) K3(-8.5,1.5) K4(-7.5,1.5) K5(-6.5,1.5) K6(-5.5,1.5) K7(-4.5,1.5) K8(-3.5,1.5) K9(-2.5,1.5) K10(-1.5,1.5) K11(-0.5,1.5) K12(0.5,1.5) K13(1.5,1.5) K14(2.5,1.5) K15(3.5,1.5) K16(4.5,1.5) K17(5.5,1.5) K18(6.5,1.5) K19(7.5,1.5) K20(8.5,1.5) K21(9.5,1.5) K22(10.5,1.5) L1(-10.5,0.5) L2(-9.5,0.5) L3(-8.5,0.5) L4(-7.5,0.5) L5(-6.5,0.5) L6(-5.5,0.5) L7(-4.5,0.5) L8(-3.5,0.5) L9(-2.5,0.5) L10(-1.5,0.5) L11(-0.5,0.5) L12(0.5,0.5) L13(1.5,0.5) L14(2.5,0.5) L15(3.5,0.5) L16(4.5,0.5) L17(5.5,0.5) L18(6.5,0.5) L19(7.5,0.5) L20(8.5,0.5) L21(9.5,0.5) L22(10.5,0.5) M1(-10.5,-0.5) M2(-9.5,-0.5) M3(-8.5,-0.5) M4(-7.5,-0.5) M5(-6.5,-0.5) M6(-5.5,-0.5) M7(-4.5,-0.5) M8(-3.5,-0.5) M9(-2.5,-0.5) M10(-1.5,-0.5) M11(-0.5,-0.5) M12(0.5,-0.5) M13(1.5,-0.5) M14(2.5,-0.5) M15(3.5,-0.5) M16(4.5,-0.5) M17(5.5,-0.5) M18(6.5,-0.5) M19(7.5,-0.5) M20(8.5,-0.5) M21(9.5,-0.5) M22(10.5,-0.5) N1(-10.5,-1.5) N2(-9.5,-1.5) N3(-8.5,-1.5) N4(-7.5,-1.5) N5(-6.5,-1.5) N6(-5.5,-1.5) N7(-4.5,-1.5) N8(-3.5,-1.5) N9(-2.5,-1.5) N10(-1.5,-1.5) N11(-0.5,-1.5) N12(0.5,-1.5) N13(1.5,-1.5) N14(2.5,-1.5) N15(3.5,-1.5) N16(4.5,-1.5) N17(5.5,-1.5) N18(6.5,-1.5) N19(7.5,-1.5) N20(8.5,-1.5) N21(9.5,-1.5) N22(10.5,-1.5) P1(-10.5,-2.5) P2(-9.5,-2.5) P3(-8.5,-2.5) P4(-7.5,-2.5) P5(-6.5,-2.5) P6(-5.5,-2.5) P7(-4.5,-2.5) P8(-3.5,-2.5) P9(-2.5,-2.5) P10(-1.5,-2.5) P11(-0.5,-2.5) P12(0.5,-2.5) P13(1.5,-2.5) P14(2.5,-2.5) P15(3.5,-2.5) P16(4.5,-2.5) P17(5.5,-2.5) P18(6.5,-2.5) P19(7.5,-2.5) P20(8.5,-2.5) P21(9.5,-2.5) P22(10.5,-2.5) R1(-10.5,-3.5) R2(-9.5,-3.5) R3(-8.5,-3.5) R4(-7.5,-3.5) R5(-6.5,-3.5) R6(-5.5,-3.5) R7(-4.5,-3.5) R8(-3.5,-3.5) R9(-2.5,-3.5) R10(-1.5,-3.5) R11(-0.5,-3.5) R12(0.5,-3.5) R13(1.5,-3.5) R14(2.5,-3.5) R15(3.5,-3.5) R16(4.5,-3.5) R17(5.5,-3.5) R18(6.5,-3.5) R19(7.5,-3.5) R20(8.5,-3.5) R21(9.5,-3.5) R22(10.5,-3.5) T1(-10.5,-4.5) T2(-9.5,-4.5) T3(-8.5,-4.5) T4(-7.5,-4.5) T5(-6.5,-4.5) T6(-5.5,-4.5) T7(-4.5,-4.5) T8(-3.5,-4.5) T9(-2.5,-4.5) T10(-1.5,-4.5) T11(-0.5,-4.5) T12(0.5,-4.5) T13(1.5,-4.5) T14(2.5,-4.5) T15(3.5,-4.5) T16(4.5,-4.5) T17(5.5,-4.5) T18(6.5,-4.5) T19(7.5,-4.5) T20(8.5,-4.5) T21(9.5,-4.5) T22(10.5,-4.5) U1(-10.5,-5.5) U2(-9.5,-5.5) U3(-8.5,-5.5) U4(-7.5,-5.5) U5(-6.5,-5.5) U6(-5.5,-5.5) U7(-4.5,-5.5) U8(-3.5,-5.5) U9(-2.5,-5.5) U10(-1.5,-5.5) U11(-0.5,-5.5) U12(0.5,-5.5) U13(1.5,-5.5) U14(2.5,-5.5) U15(3.5,-5.5) U16(4.5,-5.5) U17(5.5,-5.5) U18(6.5,-5.5) U19(7.5,-5.5) U20(8.5,-5.5) U21(9.5,-5.5) U22(10.5,-5.5) V1(-10.5,-6.5) V2(-9.5,-6.5) V3(-8.5,-6.5) V4(-7.5,-6.5) V5(-6.5,-6.5) V6(-5.5,-6.5) V7(-4.5,-6.5) V8(-3.5,-6.5) V9(-2.5,-6.5) V10(-1.5,-6.5) V11(-0.5,-6.5) V12(0.5,-6.5) V13(1.5,-6.5) V14(2.5,-6.5) V15(3.5,-6.5) V16(4.5,-6.5) V17(5.5,-6.5) V18(6.5,-6.5) V19(7.5,-6.5) V20(8.5,-6.5) V21(9.5,-6.5) V22(10.5,-6.5) W1(-10.5,-7.5) W2(-9.5,-7.5) W3(-8.5,-7.5) W4(-7.5,-7.5) W5(-6.5,-7.5) W6(-5.5,-7.5) W7(-4.5,-7.5) W8(-3.5,-7.5) W9(-2.5,-7.5) W10(-1.5,-7.5) W11(-0.5,-7.5) W12(0.5,-7.5) W13(1.5,-7.5) W14(2.5,-7.5) W15(3.5,-7.5) W16(4.5,-7.5) W17(5.5,-7.5) W18(6.5,-7.5) W19(7.5,-7.5) W20(8.5,-7.5) W21(9.5,-7.5) W22(10.5,-7.5) Y1(-10.5,-8.5) Y2(-9.5,-8.5) Y3(-8.5,-8.5) Y4(-7.5,-8.5) Y5(-6.5,-8.5) Y6(-5.5,-8.5) Y7(-4.5,-8.5) Y8(-3.5,-8.5) Y9(-2.5,-8.5) Y10(-1.5,-8.5) Y11(-0.5,-8.5) Y12(0.5,-8.5) Y13(1.5,-8.5) Y14(2.5,-8.5) Y15(3.5,-8.5) Y16(4.5,-8.5) Y17(5.5,-8.5) Y18(6.5,-8.5) Y19(7.5,-8.5) Y20(8.5,-8.5) Y21(9.5,-8.5) Y22(10.5,-8.5)
  silkscreen extent -12.27,-11.5 11.5,11.5, body extent -11.5,-11.5 11.5,11.5, height 2.54
FP-002-15547-MFG [mm]
  rect 1.9x0.6 smd paste+0 mask+0: 1(-4.6,4.445) 2(-4.6,3.175) 3(-4.6,1.905) 4(-4.6,0.635) 5(-4.6,-0.635) 6(-4.6,-1.905) 7(-4.6,-3.175) 8(-4.6,-4.445) 9(4.6,-4.445) 10(4.6,-3.175) 11(4.6,-1.905) 12(4.6,-0.635) 13(4.6,0.635) 14(4.6,1.905) 15(4.6,3.175) 16(4.6,4.445)
  silkscreen extent -6.25,-5.25 2.8,5.25, body extent -5.65,-5.5 5.65,5.5, height 0.25
FP-002-18827-MFG [mm]
  rrect100% 0.95x0.45 smd paste+0 mask+0: 1(-3.9,1.905) 2(-3.9,0.635) 3(-3.9,-0.635) 4(-3.9,-1.905) 5(3.9,-1.905) 6(3.9,-0.635) 7(3.9,0.635) 8(3.9,1.905)
  rect 4.75x4.9 smd paste+0 mask+0: 9(0,0)
  silkscreen extent -5.18,-3.05 4.05,3.05, body extent -4.48,-3.15 4.48,3.15, height 0.25
FP-BNX_L12MM2_W11MM2_T8MM-MFG [mm]
  rect 1.85x1.85 hole 1.2 paste-2539.97 mask+0: 1(2.5,2.5)
  round 1.85 hole 1.2 paste-2539.97 mask+0: 2(2.5,-2.5) 3(-2.5,2.5) 4(-2.5,-2.5) 5(0,0) 6(5,0)
  silkscreen extent -6.1,-5.6 6.82,5.6, body extent -6.2,-5.7 6.2,5.7, height 0.25
FP-CDFN2520-4LD-PL-1-MFG [mm]
  rect 0.85x0.65 smd paste+0 mask+0: 1(-0.775,0.825) 2(-0.775,-0.825) 3(0.775,-0.825) 4(0.775,0.825)
  silkscreen extent -1.92,-0.13 1.02,0.95, body extent -1.3,-1.38 1.3,1.38, height 0.25
FP-CL03-IPC_B [mil]
  rect 17.88x14.28 smd paste+0 mask+0: 1(-11.98,0) 2(11.98,0)
  silkscreen extent -21,-23 21,23, body extent -12,-6 12,6, height 13
FP-DA-T263-201E-TR-MFG [mil]
  rect 60x540 smd paste+0 mask+0: 1(-280,0) 2(280,0)
  silkscreen extent -516,-256 516,256, body extent -520,-274 520,274, height 10
FP-LS8-8-05-08-1852-MFG [mm]
  rect 1.5x0.7 smd paste+0 mask+0: 1(-2.15,1.27) 2(-2.15,0) 3(-2.15,-1.27) 5(2.15,-1.27) 6(2.15,0) 7(2.15,1.27)
  rect 0.7x1.5 smd paste+0 mask+0: 4(0,-2.15)
  rect 0.7x2.5 smd paste+0 mask+0: 8(0,1.75)
  silkscreen extent -3.67,-2.58 2.58,2.58, body extent -3,-3 3,3.1, height 0.25
FP-MSE-12-05-08-1666-IPC_B [mm]
  rect 1.54x0.455 smd paste+0 mask+0: 1(-2.11,1.625)
  rrect100% 1.54x0.455 smd paste+0 mask+0: 2(-2.11,0.975) 3(-2.11,0.325) 4(-2.11,-0.325) 5(-2.11,-0.975) 6(-2.11,-1.625) 7(2.11,-1.625) 8(2.11,-0.975) 9(2.11,-0.325) 10(2.11,0.325) 11(2.11,0.975) 12(2.11,1.625)
  rect 1.753x2.947 smd paste-1000 mask+0: 13(0,0)
  silkscreen extent -3.51,-2.7 2.02,2.7, body extent -3.13,-2.27 3.13,2.27, height 0.25
FP-S2B-ZR_LF_SN-MFG [mm]
  rect 1.2x1.2 hole 0.7 paste-2539.97 mask+0: 1(-0.75,1.6)
  round 1.2 hole 0.7 paste-2539.97 mask+0: 2(0.75,1.6)
  silkscreen extent -2.25,-3 2.25,3.52, body extent -2.35,-3.1 2.35,3.1, height 0.25
FP-XAL40-MFG [mm]
  rect 0.98x3.4 smd paste+0 mask+0: 1(-1.185,0) 2(1.185,0)
  silkscreen extent -2.15,-2.15 2.15,2.15, body extent -2.25,-2.25 2.25,2.25, height 0.25
FP-XFL4020-MFG [mm]
  rect 0.98x3.4 smd paste+0 mask+0: 1(-1.185,0) 2(1.185,0)
  silkscreen extent -2.77,-2.15 2.15,2.15, body extent -2.25,-2.25 2.25,2.25, height 0.25
LED-0805 [mm] "SMD LED, 805, Body 2.0 x 1.3 mm (LxW typ)"
  rect 1.15x1.4 smd: 1(-0.975,0) 2(0.975,0)
  silkscreen extent -1.85,-0.6 -1.85,0.6, body extent -1,-0.62 1,0.63, height 0.75
LIGO-LOGO-SM [mil] "Smaller Ligo Logo"
  silkscreen extent -154,4 -36,122
MSD7342 [mil] "Common mode choke, MSD series"
  rect 43x103 smd: 1(67,10) 2(0,10) 3(0,-223) 4(67,-223)
  silkscreen extent -116,-256 184,70, body extent -114,-253 180,41, height 181
MSOP8 [mm] "MSOP Plastic Small-Outline Package"
  rect 0.42x1.6 smd: 1(-0.975,-2.205) 2(-0.325,-2.205) 3(0.325,-2.205) 4(0.975,-2.205) 5(0.975,2.195) 6(0.325,2.195) 7(-0.325,2.195) 8(-0.975,2.195)
  silkscreen extent -1.3,-0.77 1.3,0.76, body extent -1.5,-2.45 1.5,2.45, height 1.15
NETTIE1_SMDTOP [mil] "Tie two nets together"
  rect 10x10 smd mask-10: 1(0,0) 2(20,0)
  Top Layer region: -10,-10 30,-10 30,10 -10,10
ONSC-SOT-23-3-318-08_V [mm] "SOT23, 3-Leads, Body 2.92x1.3mm, Pitch 0.95mm"
  rect 0.9x0.8 smd: 1(-1,0.95) 2(-1,-0.95) 3(1,0)
  silkscreen extent -1.12,-1.46 0.65,2.03, body extent -0.65,-1.46 0.65,1.46, height 1.11
P50E-080-SR1 [mil] "3M Pak 50 Boardmount Plug"
  rect 50x50 hole 35: 1(-25,100)
  round 50 hole 35: 2(-25,-50) 3(-75,25) 4(-75,-125) 5(-125,100) 6(-125,-50) 7(-175,25) 8(-175,-125) 9(-225,100) 10(-225,-50) 11(-275,25) 12(-275,-125) 13(-325,100) 14(-325,-50) 15(-375,25) 16(-375,-125) 17(-425,100) 18(-425,-50) 19(-475,25) 20(-475,-125) 21(-525,100) 22(-525,-50) 23(-575,25) 24(-575,-125) 25(-625,100) 26(-625,-50) 27(-675,25) 28(-675,-125) 29(-725,100) 30(-725,-50) 31(-775,25) 32(-775,-125) 33(-825,100) 34(-825,-50) 35(-875,25) 36(-875,-125) 37(-925,100) 38(-925,-50) 39(-975,25) 40(-975,-125) 41(-1025,100) 42(-1025,-50) 43(-1075,25) 44(-1075,-125) 45(-1125,100) 46(-1125,-50) 47(-1175,25) 48(-1175,-125) 49(-1225,100) 50(-1225,-50) 51(-1275,25) 52(-1275,-125) 53(-1325,100) 54(-1325,-50) 55(-1375,25) 56(-1375,-125) 57(-1425,100) 58(-1425,-50) 59(-1475,25) 60(-1475,-125) 61(-1525,100) 62(-1525,-50) 63(-1575,25) 64(-1575,-125) 65(-1625,100) 66(-1625,-50) 67(-1675,25) 68(-1675,-125) 69(-1725,100) 70(-1725,-50) 71(-1775,25) 72(-1775,-125) 73(-1825,100) 74(-1825,-50) 75(-1875,25) 76(-1875,-125) 77(-1925,100) 78(-1925,-50) 79(-1975,25) 80(-1975,-125)
  round 110 hole 93: 81(200,-50) 82(-2200,-50)
  silkscreen extent -2325,-552 325,150, body extent -2298,-546 298,139, height 280
PCIeX4-GF-2D-1000-1K-O64 [mm] "Golden finger, PCIeX4, Dual, Opposite, Pitch 1mm, 64-Position"
  rect 0.7x3.2 smd far side paste-1: A1(-9.5,0.5)
  rect 0.7x4.2 smd far side paste-1: A2(-8.5,0) A3(-7.5,0) A4(-6.5,0) A5(-5.5,0) A6(-4.5,0) A7(-3.5,0) A8(-2.5,0) A9(-1.5,0) A10(-0.5,0) A11(0.5,0) A12(3.5,0) A13(4.5,0) A14(5.5,0) A15(6.5,0) A16(7.5,0) A17(8.5,0) A18(9.5,0) A19(10.5,0) A20(11.5,0) A21(12.5,0) A22(13.5,0) A23(14.5,0) A24(15.5,0) A25(16.5,0) A26(17.5,0) A27(18.5,0) A28(19.5,0) A29(20.5,0) A30(21.5,0) A31(22.5,0) A32(23.5,0)
  rect 0.7x4.2 smd paste-1: B1(-9.5,0) B2(-8.5,0) B3(-7.5,0) B4(-6.5,0) B5(-5.5,0) B6(-4.5,0) B7(-3.5,0) B8(-2.5,0) B9(-1.5,0) B10(-0.5,0) B11(0.5,0) B12(3.5,0) B13(4.5,0) B14(5.5,0) B15(6.5,0) B16(7.5,0) B18(9.5,0) B19(10.5,0) B20(11.5,0) B21(12.5,0) B22(13.5,0) B23(14.5,0) B24(15.5,0) B25(16.5,0) B26(17.5,0) B27(18.5,0) B28(19.5,0) B29(20.5,0) B30(21.5,0) B32(23.5,0)
  rect 0.7x3.2 smd paste-1: B17(8.5,0.5) B31(22.5,0.5)
QFN50P300X300X100-17N [mm]
  rrect25% 0.86x0.26 smd: 1(-1.435,0.75) 2(-1.435,0.25) 3(-1.435,-0.25) 4(-1.435,-0.75) 9(1.435,-0.75) 10(1.435,-0.25) 11(1.435,0.25) 12(1.435,0.75)
  rrect25% 0.26x0.86 smd: 5(-0.75,-1.435) 6(-0.25,-1.435) 7(0.25,-1.435) 8(0.75,-1.435) 13(0.75,1.435) 14(0.25,1.435) 15(-0.25,1.435) 16(-0.75,1.435)
  rect 1.68x1.68 smd paste-2: 17(0,0)
  round 0.4 hole 0.2 mask+0: 18(0,0) 19(-0.58,0.58) 20(0.58,0.58) 21(-0.58,-0.58) 22(0.58,-0.58)
  silkscreen extent -2.57,-1.5 1.5,1.5, body extent -1.5,-1.5 1.5,1.5, height 1
SLAB-TSSOP-16_L [mm] "SOP, 16-Leads, Body 5.1x4.5mm, Pitch 0.65mm, IPC High Density"
  oval 1.25x0.35 smd: 1(-2.825,2.275) 2(-2.825,1.625) 3(-2.825,0.975) 4(-2.825,0.325) 5(-2.825,-0.325) 6(-2.825,-0.975) 7(-2.825,-1.625) 8(-2.825,-2.275) 9(2.825,-2.275) 10(2.825,-1.625) 11(2.825,-0.975) 12(2.825,-0.325) 13(2.825,0.325) 14(2.825,0.975) 15(2.825,1.625) 16(2.825,2.275)
  silkscreen extent -2.95,-2.55 1.8,3.12, body extent -2.25,-2.55 2.25,2.55, height 1.2
SO-8_N [mm] "SOIC, 8-Leads, Body 4.9x3.9mm, Pitch 1.27mm, IPC Medium Density"
  oval 2.2x0.6 smd: 1(-2.4,1.905) 2(-2.4,0.635) 3(-2.4,-0.635) 4(-2.4,-1.905) 5(2.4,-1.905) 6(2.4,-0.635) 7(2.4,0.635) 8(2.4,1.905)
  silkscreen extent -2.52,-2.5 0.9,2.88, body extent -1.95,-2.45 1.95,2.45, height 1.75
SO-G3/C2.25 [mm] "SOT-23; 3 Leads; Body 3.0 x 2.5 mm, inc. leads (LxW max)"
  rect 0.95x1 smd: 1(-0.95,-1.125) 2(0.95,-1.125) 3(0,1.125)
  silkscreen extent -2.1,-1.25 1.32,1.13, body extent -1.45,-1.4 1.45,1.4, height 1.3
SO-G5/E2.4 [mm] "Small Outline; 5 Leads; Body 3.6 x 3.6 mm, inc. leads (LxW max)"
  rect 0.55x1.45 smd: 1(-0.95,-1.35) 2(0,-1.35) 3(0.95,-1.35) 4(0.95,1.35) 5(-0.95,1.35)
  silkscreen extent -1.67,-2.53 1.55,1.2, body extent -1.45,-1.4 1.45,1.4, height 1.45
SO-G6/E2.4 [mm] "Small Outline; 6 Leads; Body 3.6 x 3.6 mm, inc. leads (LxW max)"
  rect 0.55x1.45 smd: 1(-0.95,-1.35) 2(0,-1.35) 3(0.95,-1.35) 4(0.95,1.35) 5(0,1.35) 6(-0.95,1.35)
  silkscreen extent -1.67,-2.52 1.55,1.2, body extent -1.45,-1.4 1.45,1.4, height 1.45
SO-G8 [mm] "Small Outline; 8 Leads; Body Width 3.9 mm; Pitch 1.27 mm"
  rect 0.6x2.2 smd: 1(-1.905,-2.6) 2(-0.635,-2.6) 3(0.635,-2.6) 4(1.905,-2.6) 5(1.905,2.6) 6(0.635,2.6) 7(-0.635,2.6) 8(-1.905,2.6)
  silkscreen extent -2.88,-2.72 2.5,1.1, body extent -2.47,-3.06 2.47,3.06, height 1.75
SON-8 [mm]
  rect 0.95x0.28 smd paste-0.14 mask+0: 1(-1.425,0.75) 2(-1.425,0.25) 3(-1.425,-0.25) 4(-1.425,-0.75) 5(1.425,-0.75) 6(1.425,-0.25) 7(1.425,0.25) 8(1.425,0.75)
  rect 1.2x2 smd paste-0.987 mask-0.991: 9(0,0)
  silkscreen extent -2.33,-1.68 1.68,1.68, body extent -1.55,-1.55 1.55,1.55, height 0.8
SW_SMD_6MM [mm]
  rect 2.75x1.4 smd: 1(0,0) 2(6.8,0) 3(0,-4) 4(6.8,-4) 5(0,-2)
  silkscreen extent -2.75,-5 6.38,1, body extent 0,-5.25 7,1.25, height 3.1
TP1-BLK [mm] "Testpoint pin, black"
  round 2.54 hole 1.58: 1(0,0)
  body extent -1.27,-1.27 1.27,1.27, height 4.89
TP1-RED [mm] "Testpoint pin, red"
  round 2.54 hole 1.58: 1(0,0)
  body extent -1.27,-1.27 1.27,1.27, height 4.89
TP1-WHT [mm] "Testpoint pin, white"
  round 2.54 hole 1.58: 1(0,0)
  body extent -1.27,-1.27 1.27,1.27, height 4.89
TP1-YLW#1 [mm] "Testpoint pin, yellow"
  round 2.54 hole 1.58: 1(0,0)
  body extent -1.27,-1.27 1.27,1.27, height 4.89
TP1-YLW#2 [mm] "Testpoint pin, yellow"
  round 2.54 hole 1.58: 1(0,-0.05)
  body extent -1.27,-1.27 1.27,1.27, height 4.89
TP2#1 [mil] "Testpoint SMD minature"
  rect 70x135 smd: 1(0,0)
  body extent -20,-52 20,53, height 60
TP2#2 [mil] "Testpoint SMD minature"
  rect 70x135 smd far side: 1(0,0)
  body extent -20,-52 20,53, height 60
TSSO3x5-G10 [mm] "Shrink Small Outline; 10 Leads; Body Width 3 mm; Pitch 0.5 mm"
  rect 0.3x1.6 smd: 1(-1,-2.05) 2(-0.5,-2.05) 3(0,-2.05) 4(0.5,-2.05) 5(1,-2.05) 6(1,2.05) 7(0.5,2.05) 8(0,2.05) 9(-0.5,2.05) 10(-1,2.05)
  silkscreen extent -1.82,-2.17 1.58,0.85, body extent -1.5,-2.54 1.5,2.49, height 1.05
TSSOP14 [mm] "Shrink Small Outline; 14 Leads; Body Width 4.4 mm; Pitch 0.65 mm"
  rect 0.3x1.65 smd: 1(-1.95,-2.775) 2(-1.3,-2.775) 3(-0.65,-2.775) 4(0,-2.775) 5(0.65,-2.775) 6(1.3,-2.775) 7(1.95,-2.775) 8(1.95,2.775) 9(1.3,2.775) 10(0.65,2.775) 11(0,2.775) 12(-0.65,2.775) 13(-1.3,2.775) 14(-1.95,2.775)
  silkscreen extent -2.77,-2.9 2.55,1.55, body extent -2.5,-3.21 2.5,3.21, height 0.94
TSSOP16 [mm] "Shrink Small Outline; 16 Leads; Body Width 4.4 mm; Pitch 0.65 mm"
  rect 0.3x1.65 smd: 1(-2.275,-2.775) 2(-1.625,-2.775) 3(-0.975,-2.775) 4(-0.325,-2.775) 5(0.325,-2.775) 6(0.975,-2.775) 7(1.625,-2.775) 8(2.275,-2.775) 9(2.275,2.775) 10(1.625,2.775) 11(0.975,2.775) 12(0.325,2.775) 13(-0.325,2.775) 14(-0.975,2.775) 15(-1.625,2.775) 16(-2.275,2.775)
  silkscreen extent -3.1,-2.9 2.55,1.55, body extent -2.5,-3.2 2.5,3.2, height 1.13
UMAX8 [mm] "Shrink Small Outline; 8 Leads; Body Width 3 mm; Pitch 0.65 mm"
  rect 0.35x1.5 smd: 1(-0.975,-2.075) 2(-0.325,-2.075) 3(0.325,-2.075) 4(0.975,-2.075) 5(0.975,2.075) 6(0.325,2.075) 7(-0.325,2.075) 8(-0.975,2.075)
  silkscreen extent -1.82,-2.2 1.52,0.92, body extent -1.5,-2.45 1.5,2.45, height 1.09
VISH-POWERPAKSO-8_A_V [mm] "SMD, 8-Leads, Body 6.15x5.155mm, Pitch 1.27mm"
  rect 1.27x0.61 smd: 1(-2.67,1.905) 2(-2.67,0.635) 3(-2.67,-0.635) 4(-2.67,-1.905)
  rect 1.02x0.61 smd: 5(2.795,-1.905) 6(2.795,-0.635) 7(2.795,0.635) 8(2.795,1.905)
  Top Layer region: -1.215,0.305 2.595,0.305 2.595,1.955 -1.215,1.955
  Top Layer region: -1.215,-1.955 2.595,-1.955 2.595,-0.305 -1.215,-0.305
  silkscreen extent -3.98,1.78 -3.73,2.03, body extent -3.08,-2.58 3.08,2.58, height 1.12
WM4200 [mil] "Locking 2 pin Molex"
  rect 62x62 hole 40: 1(0,0)
  round 62 hole 40: 2(100,0)
  silkscreen extent -50,-125 150,125, body extent -47,-122 147,128, height 420

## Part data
C1: library part ChipCap, "C2220 22u Ruby", Part Number=16MU226MD35750, Supplier Part Number 1=1189-2516-1-ND
C2 C37 C55 C165 C177 C262 C512: library part ChipCap, "C0805 100n", Part Number=KGM21NR71H104KM, Supplier Part Number 1=478-KGM21NR71H104KMCT-ND
C3A C3B C3C C3D C3E C3F C3G C3H C11A C11B C11C C11D C11E C11F C11G C11H C19A C19B C19C C19D C19E C19F C19G C19H C27A C27B C27C C27D C27E C27F C27G C27H: library part ChipCap, "C0402 3.3n", Part Number=GRM1555C1H332GE01D, Supplier Part Number 1=490-GRM1555C1H332GE01DCT-ND
C4 C6 C61 C284 C285 C286: library part ChipCap, "C0402 10n", Part Number=CC0402KRX7R9BB103, Supplier Part Number 1=311-1349-1-ND
C5 C151: library part ChipCap, "C0402 NL"
C7 C8: library part ChipCap, "C0603 10u", Part Number=GRM188Z71A106KA73D, Supplier Part Number 1=490-GRM188Z71A106KA73DCT-ND
C35 C36 C39 C40 C41 C42 C48 C50 C51 C52 C56 C58 C59 C60 C65 C66 C78 C79 C101 C102 C103 C104 C110 C116 C117 C141 C142 C143 C144 C148 C149 C150 C157 C158 C163 C187 C201 C216 C228 C229 C236 C256 C269 C274 C275 C282 C287: library part ChipCap, "C0402 100n", Part Number=CL05B104KA5NNNC, Supplier Part Number 1=1276-6720-1-ND
C38 C46: library part "CapPolypropylene ECQPZ", "Polypropylene Film Capacitor, radial lead", Part Number=399-13063-ND
C43 C44 C45 C147 C208 C209 C248 C264: library part ChipCap, "C0402 1.0n", Part Number=0402N102J250CT, Supplier Part Number 1=1292-1246-1-ND
C47 C49 C53 C63 C67 C118 C119 C156 C159 C161 C237 C270: library part ChipCap, "C0603 1.0u", Part Number=CL10B105KA8NNNC, Supplier Part Number 1=1276-1184-1-ND
C54 C68 C69 C111 C126 C127 C136 C137 C138 C139 C152 C154 C155 C162 C193 C203 C241 C242 C258: library part ChipCap, "C0805 10u", Part Number=CL21A106KAYNNNG, Supplier Part Number 1=1276-6454-1-ND
C57 C64 C72 C73 C140 C145 C344A C344B C344C C344D C344E C344F C344G C344H: library part ChipCap, "C0402 1.0u", Part Number=C0402C105K4PACTU, Supplier Part Number 1=490-10017-1-ND
C62 C93 C94 C95 C96 C146: library part ChipCap, "C0402 100p", Part Number=KGM05ACG1H101JH, Supplier Part Number 1=478-KGM05ACG1H101JHCT-ND
C70 C71: library part ChipCap, "C0402 1.8n", Part Number=C0402C182J3GACTU, Supplier Part Number 1=399-17370-1-ND
C74: library part ChipCap, "C0402 5.6n", Part Number=GRM1555C1H562GE01D, Supplier Part Number 1=490-GRM1555C1H562GE01DCT-ND
C75: library part ChipCap, "C0402 2.7n", Part Number=C0402C272K3RAC7867, Supplier Part Number 1=399-14439-1-ND
C76 C77 C114 C115 C153 C160 C166 C174 C185 C271 C272: library part ChipCap, "C1206 47u", Part Number=C3216X5R1E476M160AC, Supplier Part Number 1=810-C3216X5R1E476M
C80 C81 C120 C121 C122 C123: library part ChipCap, "C1210 3.3u Ruby", Part Number=16MU335MB33225, Supplier Part Number 1=1189-2517-1-ND
C82 C83 C84 C85: library part ChipCap, "C0402 47n", Part Number=0402B473J250CT, Supplier Part Number 1=1292-1213-1-ND
C86 C87 C88 C89 C90 C91 C92 C105 C106 C107 C112 C113 C128 C129 C130 C131 C132 C133 C134 C135: library part ChipCap, "C1210 10u", Part Number=CL32B106KAULNNE, Supplier Part Number 1=1276-3322-1-ND
C97 C98 C99 C100: library part ChipCap, "C1206 2.2u", Part Number=C1206C225J5RECAUTO, Supplier Part Number 1=399-C1206C225J5RECAUTOCT-ND
C108 C109: library part ChipCap, "C2220 47u", Part Number=CGA9N3X7R1C476M230KB, Supplier Part Number 1=445-7935-1-ND
C124 C125 C164 C168 C171 C176 C182 C183 C224 C225 C226 C227 C238 C239 C240 C249 C251 C252 C254 C255 C259 C265: library part ChipCap, "C0603 4.7u", Part Number=CL10B475KQ8NQNC, Supplier Part Number 1=1276-2087-1-ND
C167 C169 C170 C172 C173 C175 C178 C179 C180 C184 C188 C189 C190 C191 C194 C195 C196 C197 C198 C199 C200 C202 C205 C206 C207 C210 C211 C212 C213 C214 C215 C217 C218 C219 C220 C222 C223 C230 C231 C232 C233 C234 C235 C243 C244 C245 C246 C247 C250 C253 C257 C260 C261 C263 C266 C267 C268: library part CMP-2010-00306-2, "C0201 470n", Part Number=CL03A474KQ3NNNC, Supplier Part Number 1=1276-1337-1-ND
C181 C186 C192 C221: library part ChipCap, "C0805 NL"
C204: library part CMP-2010-00306-2, "C0201 NL"
C273 C276 C277 C278 C279 C280 C281 C283: library part ChipCap, "C0402 220n", Part Number=TMK105B7224KV-FR, Supplier Part Number 1=587-6021-1-ND
C288A C288B C288C C288D C288E C288F C288G C288H C289A C289B C289C C289D C289E C289F C289G C289H C304A C304B C304C C304D C304E C304F C304G C304H C312A C312B C312C C312D C312E C312F C312G C312H: library part ChipCap, "C0402 10u", Part Number=CC0402MRX5R6BB106, Supplier Part Number 1=13-CC0402MRX5R6BB106CT-ND
C320A C320B C320C C320D C320E C320F C320G C320H C328A C328B C328C C328D C328E C328F C328G C328H C336A C336B C336C C336D C336E C336F C336G C336H C352A C352B C352C C352D C352E C352F C352G C352H C384A C384B C384C C384D C384E C384F C384G C384H C385A C385B C385C C385D C385E C385F C385G C385H C400A C400B C400C C400D C400E C400F C400G C400H C401A C401B C401C C401D C401E C401F C401G C401H C416A C416B C416C C416D C416E C416F C416G C416H C424A C424B C424C C424D C424E C424F C424G C424H C432A C432B C432C C432D C432E C432F C432G C432H C440A C440B C440C C440D C440E C440F C440G C440H C448A C448B C448C C448D C448E C448F C448G C448H C449A C449B C449C C449D C449E C449F C449G C449H C464A C464B C464C C464D C464E C464F C464G C464H C465A C465B C465C C465D C465E C465F C465G C465H C480A C480B C480C C480D C480E C480F C480G C480H C488A C488B C488C C488D C488E C488F C488G C488H C496A C496B C496C C496D C496E C496F C496G C496H C504A C504B C504C C504D C504E C504F C504G C504H: library part ChipCap, "C0201 100n", Part Number=GRM033Z71C104KE14D, Supplier Part Number 1=490-GRM033Z71C104KE14DCT-ND
C360A C360B C360C C360D C360E C360F C360G C360H: library part ChipCap, "C0201 2.2u", Part Number=GRM033R61A225KE47D, Supplier Part Number 1=490-13227-1-ND
C361A C361B C361C C361D C361E C361F C361G C361H C383A C383B C383C C383D C383E C383F C383G C383H: library part ChipCap, "C0201 1.0u", Part Number=CL03A105KP3NSNC, Supplier Part Number 1=1276-6795-1-ND
D1 D2: "Single diode", Part Number=BAS16D-E3-08, Supplier Part Number 1=112-BAS16D-E3-08CT-ND
D3: library part DIODE_ZENER, "Single zener diode 12V", Part Number=BZT52C12-13-F, Supplier Part Number 1=BZT52C1213-FDICT-ND
D4: library part DIODE_SHOTTKY, Part Number=LSM115JE3/TR13, Supplier Part Number 1=150-LSM115JE3/TR13CT-ND
D5 D6 D7 D8: library part DIODE_SHOTTKY, Part Number=DFLS230-7, Supplier Part Number 1=DFLS230DICT-ND
D9 D10: library part DIODE_SHOTTKY, "Single shottky diode", Part Number=CDBA340L-G, Supplier Part Number 1=641-1258-1-ND
DS1 DS2 DS3 DS4 DS5 DS6: "Panel mount LED", Part Number=L71517CT-ND
FL1 FL2: library part CMP-2000-05960-2, "FILTER LC TH", Supplier Part Number 1=490-5055-ND
FR1 FR2 FR3 FR4 FR5 FR6 FR7 FR8 FR9 FR10 FR11 FR12: library part BLM31PG121SN1, "ferrite bead, 120Ohm at 100MHz, 1206", Part Number=BLM31PG121SN1L, Supplier Part Number 1=490-1056-1-ND
J1: library part CMP-2000-07021-2, "CONN HEADER R/A 2POS 1.5MM", Part Number=S2B-ZR, Supplier Part Number 1=455-1669-ND
J2: "Connector", Part Number=WM10869-ND
L1 L2: library part CMP-2000-05090-4, "INDUCTOR, 2.2UH, 8A, 20%, 38MHZ, REEL", Supplier Part Number 1=2457-XFL4020-222MEC-ND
